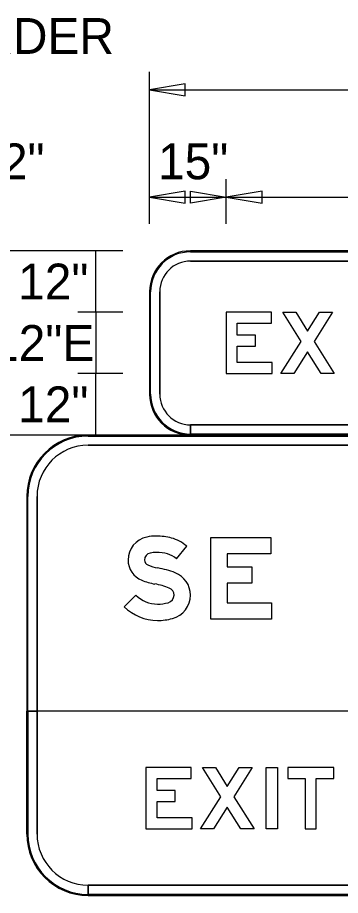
# Model space of a CAD drawing. Extents: x 2149934 to 2150188, y 145114 to 145238.
# Drawn here: x 2149961.24 to 2149966.51, y 145196.69 to 145211 of the extents above; entities that cross this region are included whole.
import ezdxf

# ---------------------------------------------------------------- set-up
doc = ezdxf.new("R2010")
doc.units = 0
for name, color, linetype in [('GSBWFILL', 7, 'Continuous'), ('GSCOLORFILL', 7, 'Continuous'), ('GSDIMS', 7, 'Continuous'), ('GSOUTLINE', 7, 'Continuous')]:
    doc.layers.add(name, color=color, linetype=linetype)

msp = doc.modelspace()

# ---------------------------------------------------------------- linework, layer by layer
at = {"layer": 'GSBWFILL'}
for p, q in [((2149975.729, 145207.195), (2149964.062, 145207.195)), ((2149964.062, 145207.029), (2149975.729, 145207.029)), ((2149963.395, 145206.529), (2149963.395, 145204.861)), ((2149963.562, 145204.861), (2149963.562, 145206.529)), ((2149964.062, 145204.195), (2149964.062, 145204.361)), ((2149975.729, 145204.361), (2149964.063, 145204.361)), ((2149964.063, 145204.361), (2149964.063, 145204.195)), ((2149975.395, 145204.195), (2149962.395, 145204.195)), ((2149964.063, 145204.195), (2149975.729, 145204.195)), ((2149962.395, 145204.028), (2149975.395, 145204.028)), ((2149961.395, 145203.195), (2149961.395, 145197.695)), ((2149961.562, 145197.695), (2149961.562, 145203.195)), ((2149961.395, 145197.695), (2149961.395, 145199.695)), ((2149961.395, 145199.695), (2149961.562, 145199.695)), ((2149976.395, 145199.695), (2149961.395, 145199.695)), ((2149961.395, 145199.695), (2149961.395, 145197.695)), ((2149961.562, 145199.695), (2149961.562, 145199.528)), ((2149961.562, 145199.528), (2149961.562, 145197.695)), ((2149962.395, 145196.695), (2149962.395, 145196.861)), ((2149962.395, 145196.861), (2149975.395, 145196.861)), ((2149975.395, 145196.861), (2149962.397, 145196.861)), ((2149962.397, 145196.861), (2149962.397, 145196.695)), ((2149975.395, 145196.695), (2149962.395, 145196.695)), ((2149962.395, 145196.695), (2149975.395, 145196.695)), ((2149962.397, 145196.695), (2149975.395, 145196.695))]:
    msp.add_line(p, q, dxfattribs=at)
for points in [[(2149965.395, 145205.375), (2149964.825, 145205.375), (2149964.825, 145205.644), (2149965.12, 145205.644), (2149965.12, 145205.824), (2149964.825, 145205.824), (2149964.825, 145206.015), (2149965.38, 145206.015), (2149965.38, 145206.195), (2149964.645, 145206.195), (2149964.645, 145205.195), (2149965.395, 145205.195)], [(2149966.193, 145205.195), (2149965.97, 145205.55), (2149965.748, 145205.195), (2149965.535, 145205.195), (2149965.864, 145205.719), (2149965.565, 145206.195), (2149965.778, 145206.195), (2149965.97, 145205.888), (2149966.163, 145206.195), (2149966.375, 145206.195), (2149966.076, 145205.719), (2149966.405, 145205.195)], [(2149965.369, 145202.528), (2149965.369, 145202.262), (2149964.662, 145202.262), (2149964.662, 145202.048), (2149965.062, 145202.048), (2149965.062, 145201.782), (2149964.662, 145201.782), (2149964.662, 145201.462), (2149965.382, 145201.462), (2149965.382, 145201.195), (2149964.395, 145201.195), (2149964.395, 145202.528)], [(2149964.087, 145197.958), (2149963.517, 145197.958), (2149963.517, 145198.227), (2149963.812, 145198.227), (2149963.812, 145198.407), (2149963.517, 145198.407), (2149963.517, 145198.598), (2149964.072, 145198.598), (2149964.072, 145198.778), (2149963.337, 145198.778), (2149963.337, 145197.778), (2149964.087, 145197.778)], [(2149964.884, 145197.778), (2149964.662, 145198.133), (2149964.439, 145197.778), (2149964.227, 145197.778), (2149964.555, 145198.302), (2149964.257, 145198.778), (2149964.469, 145198.778), (2149964.662, 145198.471), (2149964.854, 145198.778), (2149965.067, 145198.778), (2149964.768, 145198.302), (2149965.097, 145197.778)], [(2149965.297, 145197.778), (2149965.297, 145198.778), (2149965.477, 145198.778), (2149965.477, 145197.778)], [(2149965.647, 145198.598), (2149965.932, 145198.598), (2149965.932, 145197.778), (2149966.112, 145197.778), (2149966.112, 145198.598), (2149966.397, 145198.598), (2149966.397, 145198.778), (2149965.647, 145198.778)]]:
    msp.add_lwpolyline(points, close=True, dxfattribs=at)
for points in [[(2149963.835, 145202.176), (2149964, 145202.387)], [(2149963.17, 145201.587), (2149962.982, 145201.397)]]:
    msp.add_lwpolyline(points, dxfattribs=at)
for centre, radius, start, end in [((2149964.062, 145206.529), 0.667, 90, 180), ((2149964.062, 145206.529), 0.5, 90, 180), ((2149964.062, 145204.861), 0.667, 180, 270), ((2149964.062, 145204.861), 0.5, 180, 270), ((2149962.395, 145203.195), 1, 90, 180), ((2149962.395, 145203.195), 0.833, 90, 180), ((2149962.395, 145197.695), 1, 180, 270), ((2149962.395, 145197.695), 1, 180, 270), ((2149962.395, 145197.695), 1, 180, 270), ((2149962.395, 145197.695), 0.833, 180, 270), ((2149962.395, 145197.695), 0.833, 180, 270)]:
    msp.add_arc(centre, radius, start, end, dxfattribs=at)
for centre, major_axis, start_param, end_param in [((2149963.427, 145202.159), (0, 0.382), 0.202758, 1.570796), ((2149963.509, 145201.764), (0, 0.785), 0, 0.202758), ((2149963.509, 145201.586), (0, 0.963), 6.026234, 6.283185), ((2149963.598, 145201.926), (0, 0.611), 5.565152, 6.026234), ((2149963.399, 145202.159), (0, 0.354), 1.570796, 2.761249), ((2149963.427, 145202.159), (0, 0.115), 0.202758, 1.570796), ((2149963.399, 145202.159), (0, 0.0872), 1.570796, 2.761249), ((2149963.509, 145201.764), (0, 0.519), 0, 0.202758), ((2149963.509, 145201.586), (0, 0.697), 6.026234, 6.283185), ((2149963.598, 145201.926), (0, 0.345), 5.523837, 6.026234), ((2149963.69, 145202.886), (0, 0.87), 2.761249, 2.95744), ((2149963.233, 145200.435), (0, 1.623), 5.918637, 6.099033), ((2149963.673, 145201.588), (0, 0.388), 4.712389, 5.918637), ((2149963.69, 145202.886), (0, 1.137), 2.761249, 2.95744), ((2149963.233, 145200.435), (0, 1.357), 5.918637, 6.099033), ((2149963.525, 145201.945), (0, 0.504), 2.360607, 3.141593), ((2149963.666, 145201.588), (0, 0.129), 3.401517, 4.712389), ((2149963.673, 145201.588), (0, 0.122), 4.712389, 5.918637), ((2149963.666, 145201.588), (0, 0.396), 3.401517, 4.712389), ((2149963.525, 145202.119), (0, 0.678), 3.141593, 3.401517), ((2149963.525, 145201.945), (0, 0.771), 2.360607, 3.141593), ((2149963.525, 145202.119), (0, 0.945), 3.141593, 3.401517)]:
    msp.add_ellipse(centre, major_axis=major_axis, ratio=0.999994, start_param=start_param, end_param=end_param, dxfattribs=at)
at = {"layer": 'GSCOLORFILL'}
for p, q in [((2149975.729, 145207.195), (2149964.062, 145207.195)), ((2149975.729, 145207.195), (2149964.062, 145207.195)), ((2149975.729, 145207.195), (2149964.062, 145207.195)), ((2149964.062, 145207.179), (2149975.729, 145207.179)), ((2149964.062, 145207.029), (2149975.729, 145207.029)), ((2149963.395, 145206.529), (2149963.395, 145204.861)), ((2149963.395, 145206.529), (2149963.395, 145204.861)), ((2149963.395, 145206.529), (2149963.395, 145204.861)), ((2149963.412, 145204.861), (2149963.412, 145206.529)), ((2149963.562, 145204.861), (2149963.562, 145206.529)), ((2149964.062, 145204.195), (2149964.062, 145204.361)), ((2149975.729, 145204.361), (2149964.063, 145204.361)), ((2149964.063, 145204.361), (2149964.063, 145204.195)), ((2149975.395, 145204.195), (2149962.395, 145204.195)), ((2149975.395, 145204.195), (2149962.395, 145204.195)), ((2149975.395, 145204.195), (2149962.395, 145204.195)), ((2149962.395, 145204.178), (2149975.395, 145204.178)), ((2149964.062, 145204.195), (2149964.062, 145204.211)), ((2149975.729, 145204.211), (2149964.062, 145204.211)), ((2149964.062, 145204.211), (2149964.062, 145204.195)), ((2149964.062, 145204.195), (2149975.729, 145204.195)), ((2149964.062, 145204.195), (2149975.729, 145204.195)), ((2149964.063, 145204.195), (2149975.729, 145204.195)), ((2149962.395, 145204.028), (2149975.395, 145204.028)), ((2149961.395, 145203.195), (2149961.395, 145197.695)), ((2149961.395, 145203.195), (2149961.395, 145197.695)), ((2149961.395, 145203.195), (2149961.395, 145197.695)), ((2149961.412, 145197.695), (2149961.412, 145203.195)), ((2149961.562, 145197.695), (2149961.562, 145203.195)), ((2149976.395, 145199.695), (2149961.395, 145199.695)), ((2149961.395, 145199.695), (2149961.395, 145197.695)), ((2149961.395, 145197.695), (2149961.395, 145199.695)), ((2149961.395, 145199.695), (2149961.562, 145199.695)), ((2149961.395, 145197.695), (2149961.395, 145199.695)), ((2149961.395, 145199.695), (2149961.412, 145199.695)), ((2149961.412, 145199.695), (2149961.412, 145199.678)), ((2149961.412, 145199.678), (2149961.412, 145197.695)), ((2149961.562, 145199.695), (2149961.562, 145199.528)), ((2149961.562, 145199.528), (2149961.562, 145197.695)), ((2149962.395, 145196.695), (2149962.395, 145196.861)), ((2149962.395, 145196.861), (2149975.395, 145196.861)), ((2149975.395, 145196.861), (2149962.397, 145196.861)), ((2149962.397, 145196.861), (2149962.397, 145196.695)), ((2149962.395, 145196.695), (2149962.395, 145196.711)), ((2149975.395, 145196.711), (2149962.395, 145196.711)), ((2149962.395, 145196.711), (2149962.395, 145196.695)), ((2149962.395, 145196.711), (2149975.395, 145196.711)), ((2149962.395, 145196.695), (2149975.395, 145196.695)), ((2149962.395, 145196.695), (2149975.395, 145196.695)), ((2149962.395, 145196.695), (2149975.395, 145196.695)), ((2149975.395, 145196.695), (2149962.395, 145196.695)), ((2149975.395, 145196.695), (2149962.395, 145196.695)), ((2149962.397, 145196.695), (2149975.395, 145196.695))]:
    msp.add_line(p, q, dxfattribs=at)
for points in [[(2149965.395, 145205.375), (2149964.825, 145205.375), (2149964.825, 145205.644), (2149965.12, 145205.644), (2149965.12, 145205.824), (2149964.825, 145205.824), (2149964.825, 145206.015), (2149965.38, 145206.015), (2149965.38, 145206.195), (2149964.645, 145206.195), (2149964.645, 145205.195), (2149965.395, 145205.195)], [(2149966.193, 145205.195), (2149965.97, 145205.55), (2149965.748, 145205.195), (2149965.535, 145205.195), (2149965.864, 145205.719), (2149965.565, 145206.195), (2149965.778, 145206.195), (2149965.97, 145205.888), (2149966.163, 145206.195), (2149966.375, 145206.195), (2149966.076, 145205.719), (2149966.405, 145205.195)], [(2149965.369, 145202.528), (2149965.369, 145202.262), (2149964.662, 145202.262), (2149964.662, 145202.048), (2149965.062, 145202.048), (2149965.062, 145201.782), (2149964.662, 145201.782), (2149964.662, 145201.462), (2149965.382, 145201.462), (2149965.382, 145201.195), (2149964.395, 145201.195), (2149964.395, 145202.528)], [(2149964.087, 145197.958), (2149963.517, 145197.958), (2149963.517, 145198.227), (2149963.812, 145198.227), (2149963.812, 145198.407), (2149963.517, 145198.407), (2149963.517, 145198.598), (2149964.072, 145198.598), (2149964.072, 145198.778), (2149963.337, 145198.778), (2149963.337, 145197.778), (2149964.087, 145197.778)], [(2149964.884, 145197.778), (2149964.662, 145198.133), (2149964.439, 145197.778), (2149964.227, 145197.778), (2149964.555, 145198.302), (2149964.257, 145198.778), (2149964.469, 145198.778), (2149964.662, 145198.471), (2149964.854, 145198.778), (2149965.067, 145198.778), (2149964.768, 145198.302), (2149965.097, 145197.778)], [(2149965.297, 145197.778), (2149965.297, 145198.778), (2149965.477, 145198.778), (2149965.477, 145197.778)], [(2149965.647, 145198.598), (2149965.932, 145198.598), (2149965.932, 145197.778), (2149966.112, 145197.778), (2149966.112, 145198.598), (2149966.397, 145198.598), (2149966.397, 145198.778), (2149965.647, 145198.778)]]:
    msp.add_lwpolyline(points, close=True, dxfattribs=at)
for points in [[(2149963.835, 145202.176), (2149964, 145202.387)], [(2149963.17, 145201.587), (2149962.982, 145201.397)]]:
    msp.add_lwpolyline(points, dxfattribs=at)
for centre, radius, start, end in [((2149964.062, 145206.529), 0.667, 90, 180), ((2149964.062, 145206.529), 0.667, 90, 180), ((2149964.062, 145206.529), 0.667, 90, 180), ((2149964.062, 145206.529), 0.65, 90, 180), ((2149964.062, 145206.529), 0.5, 90, 180), ((2149964.062, 145204.861), 0.667, 180, 270), ((2149964.062, 145204.861), 0.667, 180, 270), ((2149964.062, 145204.861), 0.667, 180, 270), ((2149964.062, 145204.861), 0.65, 180, 270), ((2149964.062, 145204.861), 0.5, 180, 270), ((2149962.395, 145203.195), 1, 90, 180), ((2149962.395, 145203.195), 1, 90, 180), ((2149962.395, 145203.195), 1, 90, 180), ((2149962.395, 145203.195), 0.983, 90, 180), ((2149962.395, 145203.195), 0.833, 90, 180), ((2149962.395, 145197.695), 1, 180, 270), ((2149962.395, 145197.695), 1, 180, 270), ((2149962.395, 145197.695), 1, 180, 270), ((2149962.395, 145197.695), 1, 180, 270), ((2149962.395, 145197.695), 1, 180, 270), ((2149962.395, 145197.695), 1, 180, 270), ((2149962.395, 145197.695), 0.983, 180, 270), ((2149962.395, 145197.695), 0.983, 180, 270), ((2149962.395, 145197.695), 0.833, 180, 270), ((2149962.395, 145197.695), 0.833, 180, 270)]:
    msp.add_arc(centre, radius, start, end, dxfattribs=at)
for centre, major_axis, start_param, end_param in [((2149963.427, 145202.159), (0, 0.382), 0.202758, 1.570796), ((2149963.509, 145201.764), (0, 0.785), 0, 0.202758), ((2149963.509, 145201.586), (0, 0.963), 6.026234, 6.283185), ((2149963.598, 145201.926), (0, 0.611), 5.565152, 6.026234), ((2149963.399, 145202.159), (0, 0.354), 1.570796, 2.761249), ((2149963.427, 145202.159), (0, 0.115), 0.202758, 1.570796), ((2149963.399, 145202.159), (0, 0.0872), 1.570796, 2.761249), ((2149963.509, 145201.764), (0, 0.519), 0, 0.202758), ((2149963.509, 145201.586), (0, 0.697), 6.026234, 6.283185), ((2149963.598, 145201.926), (0, 0.345), 5.523837, 6.026234), ((2149963.69, 145202.886), (0, 0.87), 2.761249, 2.95744), ((2149963.233, 145200.435), (0, 1.623), 5.918637, 6.099033), ((2149963.673, 145201.588), (0, 0.388), 4.712389, 5.918637), ((2149963.69, 145202.886), (0, 1.137), 2.761249, 2.95744), ((2149963.233, 145200.435), (0, 1.357), 5.918637, 6.099033), ((2149963.525, 145201.945), (0, 0.504), 2.360607, 3.141593), ((2149963.666, 145201.588), (0, 0.129), 3.401517, 4.712389), ((2149963.673, 145201.588), (0, 0.122), 4.712389, 5.918637), ((2149963.666, 145201.588), (0, 0.396), 3.401517, 4.712389), ((2149963.525, 145202.119), (0, 0.678), 3.141593, 3.401517), ((2149963.525, 145201.945), (0, 0.771), 2.360607, 3.141593), ((2149963.525, 145202.119), (0, 0.945), 3.141593, 3.401517)]:
    msp.add_ellipse(centre, major_axis=major_axis, ratio=0.999994, start_param=start_param, end_param=end_param, dxfattribs=at)
at = {"layer": 'GSDIMS'}
for p, q in [((2149963.395, 145209.383), (2149963.395, 145210.112)), ((2149963.395, 145209.821), (2149976.395, 145209.821)), ((2149963.395, 145207.633), (2149963.395, 145209.383)), ((2149963.395, 145207.633), (2149963.395, 145208.362)), ((2149964.645, 145207.633), (2149964.645, 145208.362)), ((2149964.645, 145207.633), (2149964.645, 145208.362)), ((2149963.395, 145208.071), (2149964.645, 145208.071)), ((2149964.645, 145208.071), (2149975.146, 145208.071)), ((2149962.958, 145207.196), (2149959.458, 145207.196)), ((2149962.958, 145207.196), (2149962.228, 145207.196)), ((2149962.52, 145206.195), (2149962.52, 145207.196)), ((2149962.958, 145206.195), (2149962.228, 145206.195)), ((2149962.958, 145206.195), (2149962.228, 145206.195)), ((2149962.52, 145206.195), (2149962.52, 145205.195)), ((2149962.958, 145205.195), (2149962.228, 145205.195)), ((2149962.958, 145205.195), (2149962.228, 145205.195)), ((2149962.52, 145204.194), (2149962.52, 145205.195)), ((2149962.958, 145204.194), (2149959.458, 145204.194)), ((2149962.958, 145204.194), (2149962.228, 145204.194))]:
    msp.add_line(p, q, dxfattribs=at)
for points in [[(2149963.395, 145209.821), (2149963.978, 145209.723), (2149963.978, 145209.918)], [(2149963.395, 145208.071), (2149963.978, 145207.973), (2149963.978, 145208.168)], [(2149964.645, 145208.071), (2149964.062, 145207.973), (2149964.062, 145208.168)], [(2149964.645, 145208.071), (2149965.228, 145207.973), (2149965.228, 145208.168)]]:
    msp.add_lwpolyline(points, close=True, dxfattribs=at)
at = {"layer": 'GSOUTLINE'}
for p, q in [((2149975.729, 145207.195), (2149964.062, 145207.195)), ((2149975.729, 145207.029), (2149964.062, 145207.029)), ((2149963.395, 145206.529), (2149963.395, 145204.861)), ((2149963.562, 145206.529), (2149963.562, 145204.861)), ((2149964.062, 145204.361), (2149975.729, 145204.361)), ((2149975.395, 145204.195), (2149962.395, 145204.195)), ((2149964.062, 145204.195), (2149975.729, 145204.195)), ((2149975.395, 145204.028), (2149962.395, 145204.028)), ((2149961.395, 145203.195), (2149961.395, 145197.695)), ((2149961.562, 145203.195), (2149961.562, 145197.695)), ((2149961.395, 145197.695), (2149961.395, 145199.695)), ((2149961.395, 145199.695), (2149961.562, 145199.695)), ((2149976.395, 145199.695), (2149961.395, 145199.695)), ((2149961.395, 145199.695), (2149961.395, 145197.695)), ((2149961.562, 145199.695), (2149961.562, 145199.528)), ((2149961.562, 145199.528), (2149961.562, 145197.695)), ((2149962.395, 145196.861), (2149975.395, 145196.861)), ((2149962.395, 145196.861), (2149975.395, 145196.861)), ((2149962.395, 145196.695), (2149975.395, 145196.695)), ((2149975.395, 145196.695), (2149962.395, 145196.695)), ((2149962.395, 145196.695), (2149975.395, 145196.695))]:
    msp.add_line(p, q, dxfattribs=at)
for points in [[(2149965.395, 145205.375), (2149964.825, 145205.375), (2149964.825, 145205.644), (2149965.12, 145205.644), (2149965.12, 145205.824), (2149964.825, 145205.824), (2149964.825, 145206.015), (2149965.38, 145206.015), (2149965.38, 145206.195), (2149964.645, 145206.195), (2149964.645, 145205.195), (2149965.395, 145205.195)], [(2149966.193, 145205.195), (2149965.97, 145205.55), (2149965.748, 145205.195), (2149965.535, 145205.195), (2149965.864, 145205.719), (2149965.565, 145206.195), (2149965.778, 145206.195), (2149965.97, 145205.888), (2149966.163, 145206.195), (2149966.375, 145206.195), (2149966.076, 145205.719), (2149966.405, 145205.195)], [(2149965.369, 145202.528), (2149965.369, 145202.262), (2149964.662, 145202.262), (2149964.662, 145202.048), (2149965.062, 145202.048), (2149965.062, 145201.782), (2149964.662, 145201.782), (2149964.662, 145201.462), (2149965.382, 145201.462), (2149965.382, 145201.195), (2149964.395, 145201.195), (2149964.395, 145202.528)], [(2149964.087, 145197.958), (2149963.517, 145197.958), (2149963.517, 145198.227), (2149963.812, 145198.227), (2149963.812, 145198.407), (2149963.517, 145198.407), (2149963.517, 145198.598), (2149964.072, 145198.598), (2149964.072, 145198.778), (2149963.337, 145198.778), (2149963.337, 145197.778), (2149964.087, 145197.778)], [(2149964.884, 145197.778), (2149964.662, 145198.133), (2149964.439, 145197.778), (2149964.227, 145197.778), (2149964.555, 145198.302), (2149964.257, 145198.778), (2149964.469, 145198.778), (2149964.662, 145198.471), (2149964.854, 145198.778), (2149965.067, 145198.778), (2149964.768, 145198.302), (2149965.097, 145197.778)], [(2149965.297, 145197.778), (2149965.297, 145198.778), (2149965.477, 145198.778), (2149965.477, 145197.778)], [(2149965.647, 145198.598), (2149965.932, 145198.598), (2149965.932, 145197.778), (2149966.112, 145197.778), (2149966.112, 145198.598), (2149966.397, 145198.598), (2149966.397, 145198.778), (2149965.647, 145198.778)]]:
    msp.add_lwpolyline(points, close=True, dxfattribs=at)
for points in [[(2149963.835, 145202.176), (2149964, 145202.387)], [(2149963.17, 145201.587), (2149962.982, 145201.397)]]:
    msp.add_lwpolyline(points, dxfattribs=at)
for centre, radius, start, end in [((2149964.062, 145206.529), 0.667, 90, 180), ((2149964.062, 145206.529), 0.5, 90, 180), ((2149964.062, 145204.861), 0.667, 180, 270), ((2149964.062, 145204.861), 0.5, 180, 270), ((2149962.395, 145203.195), 1, 90, 180), ((2149962.395, 145203.195), 0.833, 90, 180), ((2149962.395, 145197.695), 1, 180, 270), ((2149962.395, 145197.695), 1, 180, 270), ((2149962.395, 145197.695), 1, 180, 270), ((2149962.395, 145197.695), 0.833, 180, 270), ((2149962.395, 145197.695), 0.833, 180, 270)]:
    msp.add_arc(centre, radius, start, end, dxfattribs=at)
for centre, major_axis, start_param, end_param in [((2149963.427, 145202.159), (0, 0.382), 0.202758, 1.570796), ((2149963.509, 145201.764), (0, 0.785), 0, 0.202758), ((2149963.509, 145201.586), (0, 0.963), 6.026234, 6.283185), ((2149963.598, 145201.926), (0, 0.611), 5.565152, 6.026234), ((2149963.399, 145202.159), (0, 0.354), 1.570796, 2.761249), ((2149963.427, 145202.159), (0, 0.115), 0.202758, 1.570796), ((2149963.399, 145202.159), (0, 0.0872), 1.570796, 2.761249), ((2149963.509, 145201.764), (0, 0.519), 0, 0.202758), ((2149963.509, 145201.586), (0, 0.697), 6.026234, 6.283185), ((2149963.598, 145201.926), (0, 0.345), 5.523837, 6.026234), ((2149963.69, 145202.886), (0, 0.87), 2.761249, 2.95744), ((2149963.233, 145200.435), (0, 1.623), 5.918637, 6.099033), ((2149963.673, 145201.588), (0, 0.388), 4.712389, 5.918637), ((2149963.69, 145202.886), (0, 1.137), 2.761249, 2.95744), ((2149963.233, 145200.435), (0, 1.357), 5.918637, 6.099033), ((2149963.525, 145201.945), (0, 0.504), 2.360607, 3.141593), ((2149963.666, 145201.588), (0, 0.129), 3.401517, 4.712389), ((2149963.673, 145201.588), (0, 0.122), 4.712389, 5.918637), ((2149963.666, 145201.588), (0, 0.396), 3.401517, 4.712389), ((2149963.525, 145202.119), (0, 0.678), 3.141593, 3.401517), ((2149963.525, 145201.945), (0, 0.771), 2.360607, 3.141593), ((2149963.525, 145202.119), (0, 0.945), 3.141593, 3.401517)]:
    msp.add_ellipse(centre, major_axis=major_axis, ratio=0.999994, start_param=start_param, end_param=end_param, dxfattribs=at)

# ---------------------------------------------------------------- texts
at = {"layer": 'GSDIMS'}
for s, p in [('BORDER', (2149959.479, 145210.404)), ('TH=2"', (2149959.479, 145208.362)), ('15"', (2149963.533, 145208.362)), ('12"', (2149961.255, 145206.404)), ('12"E', (2149960.83, 145205.403)), ('12"', (2149961.255, 145204.403))]:
    msp.add_text(s, height=0.5833, dxfattribs=at).set_placement(p)

doc.saveas('drawing.dxf')
